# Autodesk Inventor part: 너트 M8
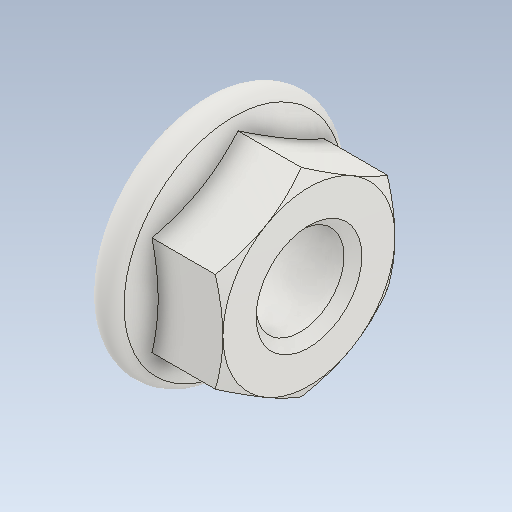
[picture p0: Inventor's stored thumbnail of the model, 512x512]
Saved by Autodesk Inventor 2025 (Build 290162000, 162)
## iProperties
Created: 2024-07
Part Number: 너트 M8
Material: 스테인리스강
Description: 플랜지붙이 6각 너트 - 일반 스레드
Document SubType Name: Modeling
Designer: 미서니
Density: 8 g/cm^3
Appearance: 기본값
Author: jhkim
Sending System: Autodesk Inventor 2025
Preprocessor: ST-DEVELOPER v20
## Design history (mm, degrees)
feature "Solid1"
node "솔리드1"
